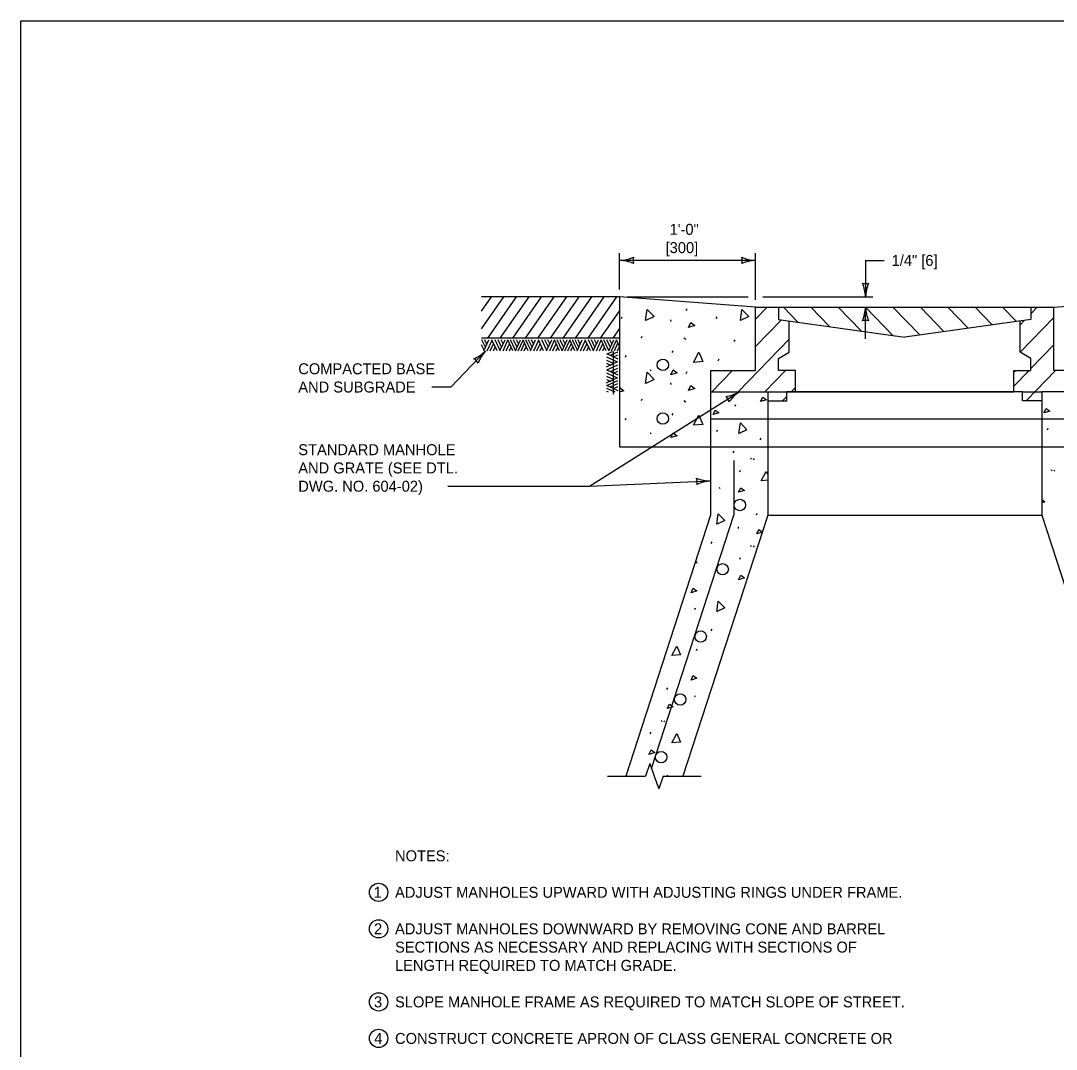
# Model space of a CAD drawing. Extents: x 49991.4 to 50021, y 49987.6 to 50011.4.
# Drawn here: x 49999.38 to 50005.05, y 49993.37 to 49999 of the extents above; entities that cross this region are included whole.
import ezdxf

# ---------------------------------------------------------------- set-up
doc = ezdxf.new("R2010")
doc.units = 0
for name, color, linetype in [('Level 1', 7, 'Continuous'), ('Level 2', 7, 'Continuous'), ('Level 3', 7, 'Continuous'), ('Level 4', 7, 'Continuous'), ('Level 6', 7, 'Continuous')]:
    doc.layers.add(name, color=color, linetype=linetype)

msp = doc.modelspace()

# ---------------------------------------------------------------- linework, layer by layer
at = {"layer": 'Level 1'}
for p, q in [((50002.6613, 49997.4869), (50001.9061, 49997.4869)), ((50001.9061, 49997.4096), (50001.9602, 49997.4869)), ((50001.9061, 49997.3116), (50002.0289, 49997.4869)), ((50001.94, 49997.2619), (50002.0976, 49997.4869)), ((50002.0087, 49997.2619), (50002.1662, 49997.4869)), ((50002.0774, 49997.2619), (50002.235, 49997.4869)), ((50002.146, 49997.2619), (50002.3036, 49997.4869)), ((50002.2147, 49997.2619), (50002.3723, 49997.4869)), ((50002.2834, 49997.2619), (50002.4409, 49997.4869)), ((50002.352, 49997.2619), (50002.5096, 49997.4869)), ((50002.4207, 49997.2619), (50002.5782, 49997.4869)), ((50002.4894, 49997.2619), (50002.6469, 49997.4869)), ((50003.4061, 49997.4313), (50002.6613, 49997.4869)), ((50002.6613, 49997.4869), (50002.6613, 49996.6669)), ((50005.0384, 49997.4313), (50005.7649, 49997.4869)), ((50003.4061, 49997.0845), (50003.4061, 49997.4313)), ((50003.4061, 49997.4313), (50005.0384, 49997.4313)), ((50003.47, 49997.4313), (50003.4061, 49997.365)), ((50003.5312, 49997.4313), (50003.5312, 49997.3641)), ((50003.5582, 49997.4313), (50003.6374, 49997.3494)), ((50003.7082, 49997.4313), (50003.8108, 49997.3248)), ((50003.8582, 49997.4313), (50003.9842, 49997.3005)), ((50004.0082, 49997.4313), (50004.1579, 49997.2762)), ((50004.1582, 49997.4313), (50004.3055, 49997.2786)), ((50004.3082, 49997.4313), (50004.4375, 49997.2972)), ((50004.4582, 49997.4313), (50004.5695, 49997.3158)), ((50004.6082, 49997.4313), (50004.7015, 49997.3344)), ((50004.7582, 49997.4313), (50004.8338, 49997.353)), ((50004.9082, 49997.4313), (50004.9133, 49997.4259)), ((50004.9133, 49997.4313), (50004.9133, 49997.3641)), ((50004.9484, 49997.4313), (50004.9133, 49997.395)), ((50005.0384, 49997.0845), (50005.0384, 49997.4313)), ((50002.558, 49997.2619), (50002.6608, 49997.4085)), ((50002.6724, 49997.3681), (50002.6767, 49997.3779)), ((50003.0265, 49997.4125), (50003.0308, 49997.4223)), ((50003.191, 49997.3681), (50003.1954, 49997.3779)), ((50005.0384, 49997.3749), (50004.8542, 49997.1838)), ((50002.9404, 49997.3615), (50002.9415, 49997.3517)), ((50003.548, 49997.3617), (50003.4061, 49997.215)), ((50003.5312, 49997.3641), (50004.2224, 49997.2669)), ((50003.5903, 49997.1838), (50003.5903, 49997.356)), ((50004.9133, 49997.3641), (50004.2224, 49997.2669)), ((50004.8788, 49997.3593), (50004.8542, 49997.3338)), ((50004.8542, 49997.1838), (50004.8542, 49997.356)), ((50002.6613, 49997.2619), (50001.9061, 49997.2619)), ((50002.6268, 49997.2619), (50002.6616, 49997.3117)), ((50002.7815, 49997.2631), (50002.7859, 49997.2728)), ((50003.0143, 49997.2631), (50003.0186, 49997.2566)), ((50003.0186, 49997.2606), (50003.023, 49997.2541)), ((50001.9196, 49997.1949), (50001.9061, 49997.2238)), ((50001.9272, 49997.2113), (50001.908, 49997.2524)), ((50001.9179, 49997.1911), (50001.9463, 49997.2524)), ((50001.9354, 49997.229), (50001.9248, 49997.2524)), ((50001.9362, 49997.1911), (50001.9634, 49997.2496)), ((50001.9537, 49997.1911), (50001.9722, 49997.2309)), ((50001.9907, 49997.1911), (50001.9621, 49997.2524)), ((50001.9711, 49997.1911), (50001.9808, 49997.2122)), ((50002.0074, 49997.1928), (50001.9798, 49997.2524)), ((50002.0162, 49997.2118), (50001.9975, 49997.2524)), ((50002.0067, 49997.1911), (50002.0351, 49997.2524)), ((50002.0242, 49997.2297), (50002.0139, 49997.2524)), ((50002.0236, 49997.1911), (50002.0507, 49997.2494)), ((50002.0412, 49997.1911), (50002.0595, 49997.2309)), ((50002.0781, 49997.1911), (50002.0494, 49997.2524)), ((50002.0591, 49997.1911), (50002.0684, 49997.2116)), ((50002.092, 49997.193), (50002.0644, 49997.2524)), ((50002.1002, 49997.2107), (50002.081, 49997.2524)), ((50002.0911, 49997.1911), (50002.1195, 49997.2526)), ((50002.1088, 49997.2292), (50002.0981, 49997.2524)), ((50002.1063, 49997.1911), (50002.1337, 49997.2505)), ((50002.1231, 49997.1911), (50002.1421, 49997.2328)), ((50002.1616, 49997.1911), (50002.1332, 49997.2524)), ((50002.1393, 49997.1911), (50002.1503, 49997.2153)), ((50002.1616, 49997.2238), (50002.1484, 49997.2524)), ((50002.1751, 49997.1949), (50002.1616, 49997.2238)), ((50002.1827, 49997.2113), (50002.1635, 49997.2524)), ((50002.1734, 49997.1911), (50002.2018, 49997.2524)), ((50002.1909, 49997.229), (50002.1802, 49997.2524)), ((50002.1917, 49997.1911), (50002.2189, 49997.2496)), ((50002.2092, 49997.1911), (50002.2277, 49997.2309)), ((50002.2461, 49997.1911), (50002.2176, 49997.2524)), ((50002.2265, 49997.1911), (50002.2362, 49997.2122)), ((50002.2629, 49997.1928), (50002.2353, 49997.2524)), ((50002.2717, 49997.2118), (50002.253, 49997.2524)), ((50002.2621, 49997.1911), (50002.2905, 49997.2524)), ((50002.2797, 49997.2297), (50002.2694, 49997.2524)), ((50002.2791, 49997.1911), (50002.3062, 49997.2494)), ((50002.2966, 49997.1911), (50002.3149, 49997.2309)), ((50002.3336, 49997.1911), (50002.3048, 49997.2524)), ((50002.3145, 49997.1911), (50002.3239, 49997.2116)), ((50002.3475, 49997.193), (50002.3199, 49997.2524)), ((50002.3557, 49997.2107), (50002.3364, 49997.2524)), ((50002.3465, 49997.1911), (50002.3749, 49997.2526)), ((50002.3643, 49997.2292), (50002.3536, 49997.2524)), ((50002.3618, 49997.1911), (50002.3892, 49997.2505)), ((50002.3785, 49997.1911), (50002.3976, 49997.2328)), ((50002.417, 49997.1911), (50002.3886, 49997.2524)), ((50002.3947, 49997.1911), (50002.4058, 49997.2153)), ((50002.417, 49997.2238), (50002.4039, 49997.2524)), ((50002.4305, 49997.1949), (50002.417, 49997.2238)), ((50002.4382, 49997.2113), (50002.4189, 49997.2524)), ((50002.4288, 49997.1911), (50002.4572, 49997.2524)), ((50002.4464, 49997.229), (50002.4357, 49997.2524)), ((50002.4471, 49997.1911), (50002.4744, 49997.2496)), ((50002.4646, 49997.1911), (50002.4831, 49997.2309)), ((50002.5016, 49997.1911), (50002.473, 49997.2524)), ((50002.482, 49997.1911), (50002.4917, 49997.2122)), ((50002.5184, 49997.1928), (50002.4907, 49997.2524)), ((50002.5271, 49997.2118), (50002.5085, 49997.2524)), ((50002.5176, 49997.1911), (50002.546, 49997.2524)), ((50002.5351, 49997.2297), (50002.5248, 49997.2524)), ((50002.5346, 49997.1911), (50002.5616, 49997.2494)), ((50002.5521, 49997.1911), (50002.5704, 49997.2309)), ((50002.589, 49997.1911), (50002.5603, 49997.2524)), ((50002.57, 49997.1911), (50002.5793, 49997.2116)), ((50002.6029, 49997.193), (50002.5753, 49997.2524)), ((50002.6111, 49997.2107), (50002.5919, 49997.2524)), ((50002.602, 49997.1911), (50002.6304, 49997.2526)), ((50002.6197, 49997.2292), (50002.609, 49997.2524)), ((50002.6172, 49997.1911), (50002.6447, 49997.2505)), ((50002.634, 49997.1911), (50002.653, 49997.2328)), ((50002.6612, 49997.2155), (50002.6441, 49997.2524)), ((50002.6502, 49997.1911), (50002.6612, 49997.2153)), ((50003.2895, 49997.2426), (50003.2939, 49997.2523)), ((50003.5903, 49997.2558), (50003.3116, 49996.9669)), ((50005.0384, 49997.2249), (50004.9133, 49997.095)), ((50002.5905, 49997.1766), (50002.6518, 49997.1482)), ((50002.5905, 49997.1583), (50002.649, 49997.131)), ((50002.5943, 49997.1748), (50002.6233, 49997.1884)), ((50002.6107, 49997.1672), (50002.6518, 49997.1865)), ((50002.6273, 49997.1884), (50002.6273, 49996.9539)), ((50002.6284, 49997.159), (50002.6518, 49997.1697)), ((50002.6938, 49997.1579), (50002.6982, 49997.1677)), ((50002.9504, 49997.1828), (50002.9548, 49997.1926)), ((50003.2018, 49997.1374), (50003.2062, 49997.1471)), ((50003.5312, 49997.1496), (50003.5903, 49997.1838)), ((50003.5312, 49997.0845), (50003.5312, 49997.1496)), ((50004.9133, 49997.1496), (50004.8542, 49997.1838)), ((50004.9133, 49997.0845), (50004.9133, 49997.1496)), ((50002.5905, 49997.1407), (50002.6303, 49997.1223)), ((50002.5905, 49997.1038), (50002.6518, 49997.1324)), ((50002.5905, 49997.1234), (50002.6116, 49997.1137)), ((50002.5905, 49997.0878), (50002.6518, 49997.0594)), ((50002.5922, 49997.087), (50002.6518, 49997.1146)), ((50002.6113, 49997.0783), (50002.6518, 49997.0969)), ((50002.8292, 49997.0887), (50002.8335, 49997.0822)), ((50002.5905, 49997.0708), (50002.6488, 49997.0438)), ((50002.5905, 49997.0533), (50002.6303, 49997.035)), ((50002.5905, 49997.0164), (50002.6518, 49997.0451)), ((50002.5905, 49997.0354), (50002.6111, 49997.0261)), ((50002.6292, 49997.0703), (50002.6518, 49997.0805)), ((50003.0265, 49997.0683), (50003.0308, 49997.0781)), ((50003.1595, 49997.0845), (50003.4061, 49997.0845)), ((50003.1598, 49997.0845), (50003.1598, 49996.2919)), ((50003.1598, 49997.0845), (50003.4061, 49997.0845)), ((50003.2804, 49997.0845), (50003.167, 49996.9669)), ((50003.5696, 49997.0845), (50003.4565, 49996.9669)), ((50003.6239, 49997.0845), (50003.5312, 49997.0845)), ((50003.6239, 49996.9669), (50003.6239, 49997.0845)), ((50004.8206, 49996.9669), (50004.8206, 49997.0845)), ((50004.8206, 49997.0845), (50004.9133, 49997.0845)), ((50004.8308, 49997.0845), (50004.8206, 49997.074)), ((50004.9031, 49997.0845), (50004.8206, 49996.999)), ((50005.048, 49997.0845), (50004.8872, 49996.918)), ((50005.285, 49997.0845), (50005.0384, 49997.0845)), ((50002.5905, 49997.0034), (50002.652, 49996.975)), ((50002.5905, 49996.9882), (50002.6363, 49996.967)), ((50002.5924, 49997.0024), (50002.6518, 49997.0301)), ((50002.6101, 49996.9943), (50002.6518, 49997.0135)), ((50002.6286, 49996.9857), (50002.6518, 49996.9963)), ((50002.9404, 49997.0173), (50002.9415, 49997.0076)), ((50003.6239, 49996.9906), (50003.6011, 49996.9669)), ((50002.5905, 49996.9714), (50002.6001, 49996.9671)), ((50002.7815, 49996.9189), (50002.7859, 49996.9287)), ((50003.0143, 49996.9189), (50003.0186, 49996.9124)), ((50003.1598, 49996.9669), (50003.4724, 49996.9669)), ((50003.4724, 49996.9669), (50003.4724, 49996.2919)), ((50003.4724, 49996.918), (50003.5774, 49996.918)), ((50003.5774, 49996.9423), (50003.5537, 49996.918)), ((50003.5774, 49996.918), (50003.5774, 49996.9669)), ((50003.5774, 49996.9669), (50003.6239, 49996.9669)), ((50004.8674, 49996.9669), (50003.5774, 49996.9669)), ((50003.6239, 49996.9669), (50004.8206, 49996.9669)), ((50004.8674, 49996.9669), (50004.8206, 49996.9669)), ((50004.8674, 49996.918), (50004.8674, 49996.9669)), ((50004.9724, 49996.918), (50004.8674, 49996.918)), ((50005.285, 49996.9669), (50004.9724, 49996.9669)), ((50004.9724, 49996.9669), (50004.9724, 49996.2919)), ((50003.0186, 49996.9164), (50003.023, 49996.91)), ((50003.2942, 49996.8894), (50003.298, 49996.8984)), ((50002.6938, 49996.8138), (50002.6982, 49996.8235)), ((50002.9504, 49996.8387), (50002.9548, 49996.8484)), ((50005.285, 49996.8169), (50003.1598, 49996.8169)), ((50003.1934, 49996.7499), (50003.1973, 49996.7589)), ((50005.0041, 49996.7592), (50005.008, 49996.7682)), ((50002.8292, 49996.7445), (50002.8335, 49996.738)), ((50003.4318, 49996.7046), (50003.436, 49996.7136)), ((50002.6613, 49996.6669), (50005.7649, 49996.6669)), ((50003.2843, 49996.6341), (50003.2882, 49996.6431)), ((50003.287, 49996.5919), (50003.287, 49996.2919)), ((50003.3785, 49996.6042), (50003.3824, 49996.5982)), ((50003.3938, 49996.6018), (50003.3977, 49996.5958)), ((50003.3194, 49996.5301), (50003.3236, 49996.5391)), ((50005.024, 49996.5415), (50005.0282, 49996.5355)), ((50005.0393, 49996.5394), (50005.0432, 49996.5334)), ((50003.2075, 49996.4431), (50003.2114, 49996.4371)), ((50003.4106, 49996.2943), (50003.4148, 49996.3033)), ((50003.1598, 49996.2919), (50002.6954, 49994.863)), ((50002.8365, 49994.9058), (50003.287, 49996.2919)), ((50003.4724, 49996.2919), (50003.008, 49994.863)), ((50003.4724, 49996.2919), (50004.9724, 49996.2919)), ((50004.9724, 49996.2919), (50005.4368, 49994.863)), ((50003.3104, 49996.2283), (50003.3113, 49996.2193)), ((50003.1637, 49996.1374), (50003.1676, 49996.1464)), ((50003.3785, 49996.1257), (50003.3824, 49996.1197)), ((50003.3938, 49996.1236), (50003.3977, 49996.1176)), ((50003.0827, 49996.0288), (50003.0866, 49996.0378)), ((50003.3194, 49996.0516), (50003.3236, 49996.0606)), ((50003.0728, 49995.775), (50003.0767, 49995.784)), ((50003.1637, 49995.6592), (50003.1676, 49995.6682)), ((50003.0827, 49995.5503), (50003.0866, 49995.5593)), ((50003.2075, 49995.4864), (50003.2096, 49995.4834)), ((50002.921, 49995.3376), (50002.9249, 49995.3466)), ((50003.0728, 49995.2965), (50003.0767, 49995.3055)), ((50002.8886, 49995.169), (50002.8925, 49995.163)), ((50002.9039, 49995.1666), (50002.9078, 49995.1606)), ((50002.8298, 49995.0949), (50002.8337, 49995.1039)), ((50002.9228, 49994.863), (50002.9249, 49994.8681))]:
    msp.add_line(p, q, dxfattribs=at)
msp.add_lwpolyline([(49999.3835, 49998.9992), (50016.7501, 49998.9992), (50016.7501, 49987.7988), (49999.3835, 49987.7988)], close=True, dxfattribs=at)
for points in [[(50002.8041, 49997.3569), (50002.8127, 49997.4188), (50002.8515, 49997.3788), (50002.8051, 49997.3573)], [(50003.3227, 49997.3569), (50003.3313, 49997.4188), (50003.3701, 49997.3788), (50003.3238, 49997.3573)], [(50003.0392, 49997.3194), (50003.0522, 49997.3465), (50003.0739, 49997.3302), (50003.0392, 49997.3194)], [(50003.0663, 49997.1287), (50003.0955, 49997.1839), (50003.1183, 49997.133), (50003.0674, 49997.1287)], [(50002.9428, 49997.0605), (50002.9558, 49997.0876), (50002.9775, 49997.0713), (50002.9428, 49997.0605)], [(50002.8041, 49997.0128), (50002.8127, 49997.0746), (50002.8515, 49997.0346), (50002.8051, 49997.0131)], [(50002.6613, 49996.9841), (50002.664, 49996.9896), (50002.6856, 49996.9734), (50002.6649, 49996.9669)], [(50003.0392, 49996.9752), (50003.0522, 49997.0023), (50003.0739, 49996.986), (50003.0392, 49996.9752)], [(50003.4331, 49996.9137), (50003.4451, 49996.9386), (50003.4652, 49996.9236), (50003.4331, 49996.9137)], [(50003.1736, 49996.8423), (50003.1856, 49996.8672), (50003.2054, 49996.8522), (50003.1736, 49996.8423)], [(50004.9843, 49996.8516), (50004.9963, 49996.8765), (50005.0161, 49996.8615), (50004.9843, 49996.8516)], [(50003.0663, 49996.7845), (50003.0955, 49996.8397), (50003.1183, 49996.7889), (50003.0674, 49996.7845)], [(50003.3149, 49996.7397), (50003.3227, 49996.7967), (50003.3584, 49996.7598), (50003.3158, 49996.7397)], [(50002.9428, 49996.7163), (50002.9558, 49996.7434), (50002.9775, 49996.7271), (50002.9428, 49996.7163)], [(50003.4376, 49996.48), (50003.4646, 49996.531), (50003.4724, 49996.5139)], [(50003.4724, 49996.483), (50003.4388, 49996.48)], [(50003.3125, 49996.417), (50003.3245, 49996.4422), (50003.3446, 49996.4272), (50003.3125, 49996.417)], [(50004.9724, 49996.378), (50004.9901, 49996.3645), (50004.9724, 49996.3591)], [(50003.1943, 49996.243), (50003.2021, 49996.3), (50003.2378, 49996.2631), (50003.1952, 49996.2433)], [(50003.4127, 49996.1893), (50003.4247, 49996.2142), (50003.4427, 49996.201)], [(50003.4421, 49996.1986), (50003.4127, 49996.1893)], [(50003.3125, 49995.9388), (50003.3245, 49995.9637), (50003.3446, 49995.9487), (50003.3125, 49995.9388)], [(50003.053, 49995.8674), (50003.065, 49995.8923), (50003.0848, 49995.8773), (50003.053, 49995.8674)], [(50003.1943, 49995.7648), (50003.2021, 49995.8218), (50003.2378, 49995.7849), (50003.1952, 49995.7648)], [(50002.948, 49995.5233), (50002.9747, 49995.5743), (50002.9957, 49995.5272), (50002.9489, 49995.5233)], [(50003.053, 49995.3892), (50003.065, 49995.4141), (50003.0848, 49995.3991), (50003.053, 49995.3892)], [(50002.9228, 49995.2326), (50002.9348, 49995.2578), (50002.9549, 49995.2428), (50002.9228, 49995.2326)], [(50002.948, 49995.0451), (50002.9747, 49995.0958), (50002.9957, 49995.049), (50002.9489, 49995.0451)], [(50002.8226, 49994.9821), (50002.8346, 49995.007), (50002.8547, 49994.992), (50002.8226, 49994.9821)], [(50002.7119, 49994.863), (50002.7122, 49994.8651), (50002.7143, 49994.863)]]:
    msp.add_lwpolyline(points, dxfattribs=at)
for centre in [(50002.8989, 49997.1147), (50002.8986, 49996.8209), (50003.3204, 49996.3474), (50003.2257, 49995.9957), (50003.1054, 49995.6273), (50002.9933, 49995.2831), (50002.8895, 49994.9674)]:
    msp.add_circle(centre, 0.0313, dxfattribs=at)
at = {"layer": 'Level 2'}
for centre in [(50001.3425, 49994.227), (50001.3425, 49994.027), (50001.3425, 49993.627), (50001.3425, 49993.4271)]:
    msp.add_circle(centre, 0.05, dxfattribs=at)
at = {"layer": 'Level 3'}
for p, q in [((50002.6613, 49997.5269), (50002.6613, 49997.7269)), ((50003.4061, 49997.4869), (50003.4061, 49997.7269)), ((50003.4061, 49997.6869), (50002.6613, 49997.6869)), ((50004.0082, 49997.6869), (50004.1109, 49997.6869)), ((50004.0082, 49997.6869), (50004.0082, 49997.4869)), ((50002.7013, 49997.4869), (50003.3661, 49997.4869)), ((50002.7361, 49997.4869), (50003.3661, 49997.4869)), ((50003.4061, 49997.4713), (50003.4061, 49997.4867)), ((50003.4461, 49997.4869), (50004.0482, 49997.4869)), ((50004.0082, 49997.2579), (50004.0082, 49997.4313)), ((50001.9281, 49997.1911), (50001.7375, 49996.9935)), ((50001.7375, 49996.9935), (50001.6348, 49996.9935)), ((50001.7375, 49996.9935), (50001.6348, 49996.9935)), ((50002.4964, 49996.4515), (50003.3161, 49996.9669)), ((50002.4964, 49996.4515), (50003.1598, 49996.4794)), ((50001.7214, 49996.4502), (50002.4964, 49996.4515))]:
    msp.add_line(p, q, dxfattribs=at)
for centre, radius, start, end in [((50002.6498, 49997.9196), 0.233, 272.8273, 292.0772), ((50002.6521, 49997.4648), 0.2223, 67.456, 87.6395), ((50002.7895, 49997.6869), 0.0548, 162.1388, 197.8612), ((50003.4152, 49997.9091), 0.2223, 247.456, 267.6395), ((50003.2779, 49997.6869), 0.0548, 342.1388, 17.8612), ((50003.4176, 49997.4542), 0.233, 92.8273, 112.0772), ((50004.0082, 49997.6152), 0.0548, 252.1388, 287.8612), ((50003.7755, 49997.4754), 0.233, 2.8273, 22.0772), ((50004.2303, 49997.4778), 0.2223, 157.456, 177.6395), ((50003.7861, 49997.4405), 0.2223, 337.456, 357.6395), ((50004.2409, 49997.4428), 0.233, 182.8273, 202.0772), ((50004.0082, 49997.3031), 0.0548, 72.1388, 107.8612), ((50001.7686, 49997.3609), 0.233, 293.952, 313.2019), ((50001.8391, 49997.0988), 0.0548, 28.168, 63.8904), ((50002.0943, 49997.0435), 0.2223, 138.3897, 158.5732), ((50003.2074, 49997.1609), 0.2223, 279.0975, 299.281), ((50003.2069, 49996.8997), 0.0548, 13.7803, 49.5027), ((50003.448, 49996.7748), 0.233, 124.4688, 143.7187), ((50003.1615, 49996.7018), 0.2223, 249.3654, 269.5489), ((50003.0316, 49996.4752), 0.0548, 344.0482, 19.7706), ((50003.179, 49996.2472), 0.233, 94.7367, 113.9866)]:
    msp.add_arc(centre, radius, start, end, dxfattribs=at)
at = {"layer": 'Level 4'}
for p, q in [((50003.4724, 49996.9669), (50003.5774, 49996.9669)), ((50004.8674, 49996.9669), (50004.9724, 49996.9669))]:
    msp.add_line(p, q, dxfattribs=at)
at = {"layer": 'Level 6'}
for p, q in [((50002.8274, 49994.9316), (50002.8031, 49994.863)), ((50002.8274, 49994.9316), (50002.8517, 49994.863)), ((50002.5954, 49994.863), (50002.8031, 49994.863)), ((50002.8517, 49994.863), (50002.876, 49994.7944)), ((50002.9003, 49994.863), (50002.876, 49994.7944)), ((50002.9003, 49994.863), (50003.108, 49994.863))]:
    msp.add_line(p, q, dxfattribs=at)

# ---------------------------------------------------------------- texts
at = {"layer": 'Level 2'}
for s, p in [('1\'-0"', (50002.9353, 49997.8269)), ('[300]', (50002.9136, 49997.7269)), ('1/4" [6]', (50004.1509, 49997.6569)), ('COMPACTED BASE', (50000.9029, 49997.0635)), ('AND SUBGRADE', (50000.9029, 49996.9635)), ('STANDARD MANHOLE', (50000.9029, 49996.6204)), ('AND GRATE (SEE DTL.', (50000.9029, 49996.5204)), ('DWG. NO. 604-02)', (50000.9029, 49996.4204)), ('NOTES:', (50001.4325, 49994.397)), ('1', (50001.3158, 49994.1971)), ('ADJUST MANHOLES UPWARD WITH ADJUSTING RINGS UNDER FRAME.', (50001.4325, 49994.197)), ('2', (50001.3173, 49993.997)), ('ADJUST MANHOLES DOWNWARD BY REMOVING CONE AND BARREL', (50001.4325, 49993.997)), ('SECTIONS AS NECESSARY AND REPLACING WITH SECTIONS OF', (50001.4325, 49993.897)), ('LENGTH REQUIRED TO MATCH GRADE.', (50001.4325, 49993.797)), ('3', (50001.3173, 49993.597)), ('SLOPE MANHOLE FRAME AS REQUIRED TO MATCH SLOPE OF STREET.', (50001.4325, 49993.597)), ('4', (50001.3185, 49993.3971)), ('CONSTRUCT CONCRETE APRON OF CLASS GENERAL CONCRETE OR ', (50001.4325, 49993.397))]:
    msp.add_text(s, height=0.06, dxfattribs=at).set_placement(p)

doc.saveas('drawing.dxf')
